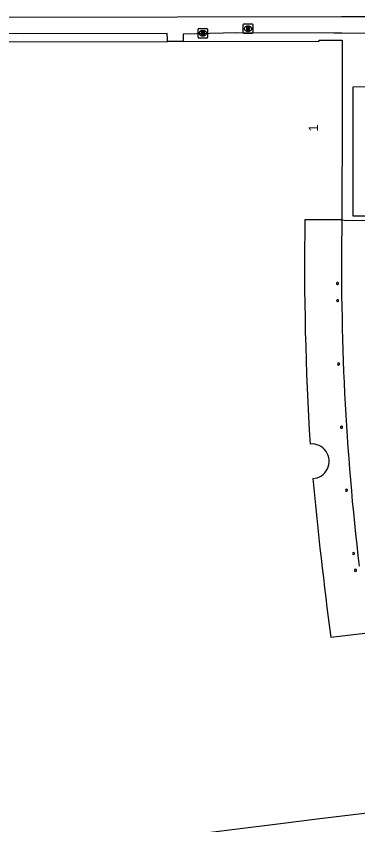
# Model space of a CAD drawing. Extents: x 161477 to 163040, y 383680 to 384868.
# Drawn here: x 162131.9 to 162168, y 384102.6 to 384187.9 of the extents above; entities that cross this region are included whole.
import ezdxf

# ---------------------------------------------------------------- set-up
doc = ezdxf.new("R2010")
doc.units = 0
for name, color, linetype in [('IMGEO_Groenvoorziening', 7, 'Continuous'), ('IMGEO_Pand', 7, 'Continuous'), ('IMGEO_Pand_nummerreeks', 7, 'Continuous'), ('IMGEO_Rioolput', 7, 'Continuous'), ('IMGEO_Voetpad_open', 7, 'Continuous')]:
    doc.layers.add(name, color=color, linetype=linetype)

msp = doc.modelspace()

# ---------------------------------------------------------------- linework, layer by layer
at = {"layer": 'IMGEO_Groenvoorziening'}
for points in [[(162147.865, 384185.24), (162147.854, 384185.518), (162147.832, 384186.078), (162132.604, 384186.048), (162111.689, 384186.117), (162098.26, 384186.018), (162062.306, 384186.012), (162061.359, 384186.012)], [(162171.652, 384166.414), (162171.68, 384166.786), (162167.472, 384166.788), (162167.473, 384167.492), (162167.49, 384180.44), (162174.149, 384180.537), (162173.964, 384185.999), (162166.287, 384186.12), (162165.447, 384186.122), (162155.137, 384186.146), (162149.501, 384186.002), (162149.508, 384185.702), (162149.52, 384185.242)]]:
    msp.add_lwpolyline(points, dxfattribs=at)
at = {"layer": 'IMGEO_Pand'}
for points in [[(162061.36, 384185.144), (162147.865, 384185.24)], [(162149.52, 384185.242), (162147.865, 384185.24)], [(162149.52, 384185.242), (162163.904, 384185.258), (162163.904, 384185.368), (162166.305, 384185.379), (162166.305, 384185.279), (162166.316, 384177.667), (162166.297, 384166.401)], [(162166.297, 384166.401), (162162.377, 384166.407)], [(162165.109, 384122.365), (162169.049, 384122.85)], [(162171.355, 384104.089), (162168.964, 384103.705), (162168.951, 384103.814), (162163.69, 384103.164), (162160.099, 384102.72), (162133.124, 384099.384), (162132.852, 384099.35)]]:
    msp.add_lwpolyline(points, dxfattribs=at)
for centre, radius, start, end in [((162474.563, 384161.839), 312.22, 179.16169, 183.5032), ((162165.827, 384159.691), 0.111, 33.52805, 253.28307), ((162165.828, 384159.69), 0.11, 252.72973, 34.08139), ((162165.838, 384157.889), 0.109, 33.54797, 302.67471), ((162165.839, 384157.889), 0.108, 302.37572, 33.84696), ((162165.939, 384151.206), 0.113, 49.57007, 310.42993), ((162165.94, 384151.206), 0.112, 310.11219, 49.88781), ((162166.257, 384144.531), 0.113, 29.67872, 300.31864), ((162166.257, 384144.531), 0.112, 300.21956, 29.7778), ((162163.116, 384140.94), 1.83, 272.79335, 95.92001), ((162720.263, 384193.963), 559.752, 185.62356, 187.34888), ((162166.777, 384137.879), 0.11, 49.41705, 317.10327), ((162166.776, 384137.879), 0.11, 317.2949, 49.22542), ((162167.514, 384131.202), 0.109, 47.76577, 316.66782), ((162167.516, 384131.202), 0.108, 316.0765, 48.35709), ((162167.725, 384129.443), 0.117, 45.99119, 313.33076), ((162167.726, 384129.443), 0.116, 312.93454, 46.38741)]:
    msp.add_arc(centre, radius, start, end, dxfattribs=at)
at = {"layer": 'IMGEO_Rioolput'}
for p, q in [((162151.167, 384186.597), (162152.019, 384186.597)), ((162155.868, 384186.156), (162155.868, 384187.008)), ((162155.943, 384187.082), (162156.795, 384187.082)), ((162156.356, 384186.862), (162156.381, 384186.862)), ((162156.869, 384187.008), (162156.869, 384186.156)), ((162151.092, 384185.671), (162151.092, 384186.523)), ((162151.603, 384185.817), (162151.578, 384185.817)), ((162151.58, 384186.377), (162151.605, 384186.377)), ((162152.093, 384186.523), (162152.093, 384185.671)), ((162156.795, 384186.082), (162155.943, 384186.082)), ((162156.379, 384186.302), (162156.354, 384186.302)), ((162152.019, 384185.597), (162151.167, 384185.597))]:
    msp.add_line(p, q, dxfattribs=at)
for points in [[(162151.167, 384186.597), (162152.019, 384186.597)], [(162155.868, 384186.156), (162155.868, 384187.008)], [(162155.943, 384187.082), (162156.795, 384187.082)], [(162156.457, 384186.78), (162156.205, 384186.782), (162156.205, 384186.382)], [(162156.383, 384186.701), (162156.329, 384186.701), (162156.329, 384186.62)], [(162156.329, 384186.62), (162156.381, 384186.62)], [(162156.869, 384187.008), (162156.869, 384186.156)], [(162151.092, 384185.671), (162151.092, 384186.523)], [(162151.681, 384186.295), (162151.429, 384186.297), (162151.429, 384185.897)], [(162151.429, 384185.897), (162151.553, 384185.897), (162151.553, 384186.059), (162151.564, 384186.059)], [(162151.607, 384186.216), (162151.553, 384186.216), (162151.553, 384186.135)], [(162151.553, 384186.135), (162151.605, 384186.135)], [(162151.611, 384186.03), (162151.682, 384185.897), (162151.822, 384185.897), (162151.757, 384186.023)], [(162152.093, 384186.523), (162152.093, 384185.671)], [(162156.795, 384186.082), (162155.943, 384186.082)], [(162156.205, 384186.382), (162156.329, 384186.382), (162156.329, 384186.544), (162156.34, 384186.544)], [(162156.387, 384186.515), (162156.458, 384186.382), (162156.598, 384186.382), (162156.533, 384186.508)], [(162152.019, 384185.597), (162151.167, 384185.597)]]:
    msp.add_lwpolyline(points, dxfattribs=at)
for centre, radius, start, end in [((162151.169, 384186.521), 0.0765, 91.55205, 178.44795), ((162151.169, 384186.521), 0.0765, 91.55205, 178.44795), ((162152.017, 384186.521), 0.0765, 1.55205, 88.44795), ((162152.017, 384186.521), 0.0765, 1.55205, 88.44795), ((162155.945, 384187.006), 0.0765, 91.55205, 178.44795), ((162155.945, 384187.006), 0.0765, 91.55205, 178.44795), ((162156.365, 384186.809), 0.19, 274.7715, 282.96867), ((162156.389, 384186.605), 0.0964, 77.00612, 93.18647), ((162156.403, 384186.662), 0.0378, 276.66336, 79.67722), ((162156.456, 384186.67), 0.109, 350.36119, 89.41601), ((162156.454, 384186.67), 0.112, 277.58423, 350.98172), ((162156.793, 384187.006), 0.0765, 1.55205, 88.44795), ((162156.793, 384187.006), 0.0765, 1.55205, 88.44795), ((162151.563, 384186.006), 0.0533, 26.02933, 88.69889), ((162151.589, 384186.324), 0.19, 274.7715, 282.96867), ((162151.613, 384186.12), 0.0964, 77.00612, 93.18647), ((162151.627, 384186.177), 0.0378, 276.66336, 79.67722), ((162151.68, 384186.185), 0.109, 350.36119, 89.41601), ((162151.678, 384186.185), 0.112, 277.58423, 350.98172), ((162151.662, 384185.97), 0.108, 29.51342, 73.79051), ((162155.945, 384186.158), 0.0765, 181.55205, 268.44795), ((162155.945, 384186.158), 0.0765, 181.55205, 268.44795), ((162156.339, 384186.491), 0.0533, 26.02933, 88.69889), ((162156.438, 384186.455), 0.108, 29.51342, 73.79051), ((162156.793, 384186.158), 0.0765, 271.55205, 358.44795), ((162156.793, 384186.158), 0.0765, 271.55205, 358.44795), ((162151.169, 384185.673), 0.0765, 181.55205, 268.44795), ((162151.169, 384185.673), 0.0765, 181.55205, 268.44795), ((162152.017, 384185.673), 0.0765, 271.55205, 358.44795), ((162152.017, 384185.673), 0.0765, 271.55205, 358.44795)]:
    msp.add_arc(centre, radius, start, end, dxfattribs=at)
for centre, major_axis, ratio, start_param, end_param in [((162156.355, 384186.582), (-0.387, 0.002), 0.722429, 4.712389, 7.853982), ((162156.38, 384186.582), (-0.39, 0.002), 0.717154, 1.570796, 4.712389), ((162151.579, 384186.097), (-0.387, 0.002), 0.722429, 4.712389, 7.853982), ((162151.604, 384186.097), (-0.39, 0.002), 0.717154, 1.570796, 4.712389)]:
    msp.add_ellipse(centre, major_axis=major_axis, ratio=ratio, start_param=start_param, end_param=end_param, dxfattribs=at)
at = {"layer": 'IMGEO_Voetpad_open'}
for points in [[(162057.006, 384186.444), (162056.999, 384186.768), (162056.979, 384187.689), (162097.018, 384187.775), (162111.682, 384187.774), (162130.783, 384187.804), (162148.931, 384187.832), (162166.246, 384187.869), (162174.081, 384187.881), (162176.282, 384187.902), (162188.794, 384187.886)], [(162166.297, 384166.401), (162166.795, 384166.359), (162171.183, 384166.409)]]:
    msp.add_lwpolyline(points, dxfattribs=at)
msp.add_arc((162434.203, 384161.419), 267.952, 178.93462, 186.76454, dxfattribs=at)

# ---------------------------------------------------------------- texts
at = {"layer": 'IMGEO_Pand_nummerreeks'}
msp.add_text('1', height=1, rotation=89.97729, dxfattribs=at).set_placement((162163.781, 384175.729))

doc.saveas('drawing.dxf')
